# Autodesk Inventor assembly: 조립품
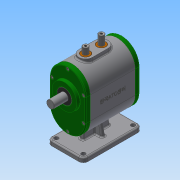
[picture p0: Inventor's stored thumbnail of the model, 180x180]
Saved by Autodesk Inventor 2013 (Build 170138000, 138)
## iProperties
Created: 2018-10
Part Number: 조립품
Document SubType Name: Assembly
Designer: Administrator
Author: Administrator
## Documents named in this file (15)
- C:\Users\Administrator\Desktop\381007V1021\조립품.iam
- C:\Users\Administrator\Desktop\381007V1021\본체.ipt
- C:\Users\Administrator\Desktop\381007V1021\가변스프링1.ipt
- C:\Users\Administrator\Desktop\381007V1021\가변스프링2.ipt
- C:\Users\Administrator\Desktop\381007V1021\뒤커버.ipt
- C:\Users\Administrator\Desktop\381007V1021\메인축.ipt
- C:\Users\Administrator\Desktop\381007V1021\베어링 608.ipt
- C:\Users\Administrator\Desktop\381007V1021\베어링 6003.ipt
- C:\Users\Administrator\Desktop\381007V1021\볼트 M4.ipt
- C:\Users\Administrator\Desktop\381007V1021\부시.ipt
- C:\Users\Administrator\Desktop\381007V1021\서브축.ipt
- C:\Users\Administrator\Desktop\381007V1021\슬라이더.ipt
- C:\Users\Administrator\Desktop\381007V1021\앞커버.ipt
- C:\Users\Administrator\Desktop\381007V1021\오일실 8 22 7.ipt
- C:\Users\Administrator\Desktop\381007V1021\오일실 17 32 8.ipt
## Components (2 placed, 2 different names)
1. 가변스프링1:1
2. 가변스프링2:1
